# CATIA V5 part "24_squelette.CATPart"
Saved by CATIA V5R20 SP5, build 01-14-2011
Part number: 24_squelette
Publications: "Plan.3", "Plan yz"
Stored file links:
  C:\Documents and Settings\anizard\Bureau\13\24_squelette.CATPart
  C:\Documents and Settings\anizard\Bureau\13\anizard.CATProduct
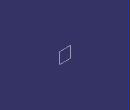
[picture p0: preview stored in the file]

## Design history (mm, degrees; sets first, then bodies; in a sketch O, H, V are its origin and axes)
Parameters
  epaisseur = 12 mm
Set1
  Plane1: linked copy from another document
Body1 (main body)
  Plane2: type Offset, RefPlane Plane1, Offset 12 {= epaisseur}, reversed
